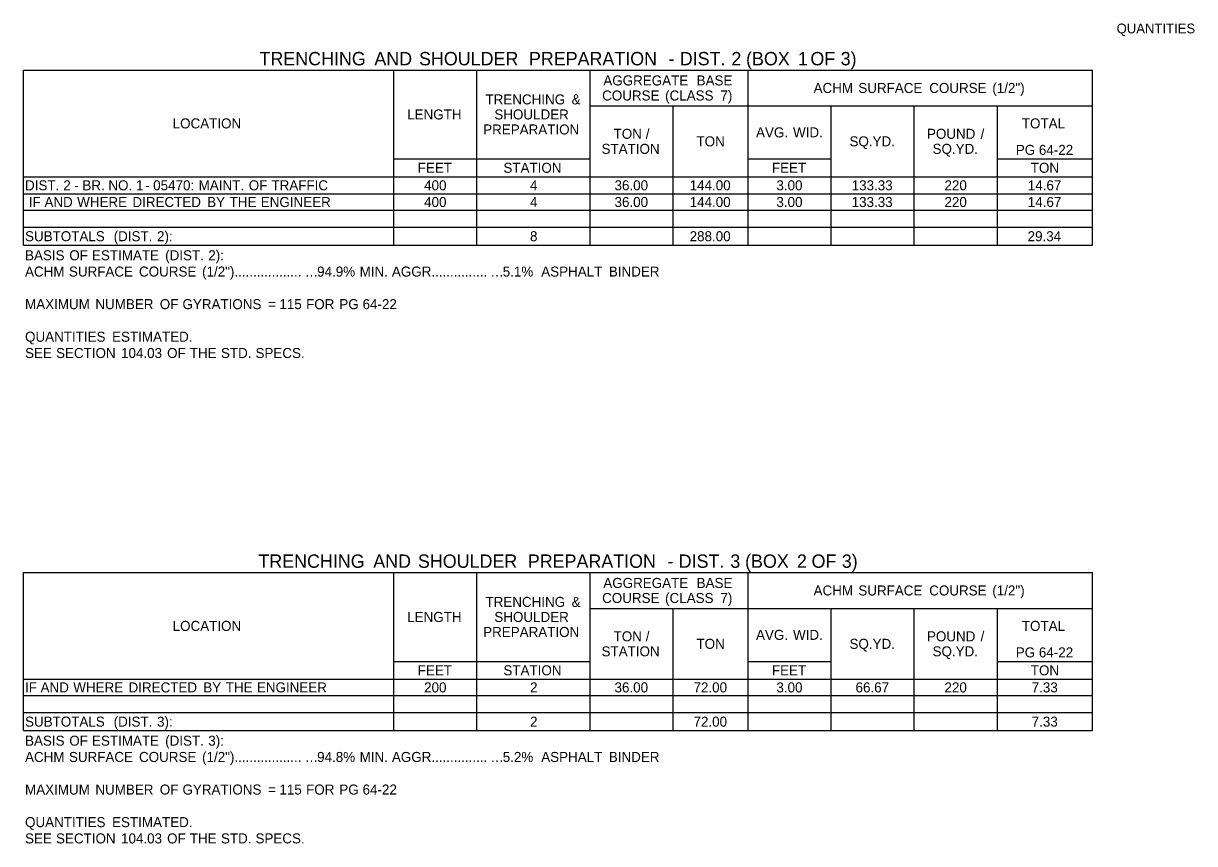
# Model space of a CAD drawing. Extents: x 544250 to 1930787, y -1948365 to 596640.
# Drawn here: x 546909 to 547610, y -1947849 to -1947358 of the extents above; entities that cross this region are included whole.
import ezdxf

# ---------------------------------------------------------------- set-up
doc = ezdxf.new("R2010")
doc.units = 0
doc.layers.add('Default', color=7, linetype='Continuous')
doc.layers.add('R_Border Prem', color=7, linetype='Continuous')

msp = doc.modelspace()

# ---------------------------------------------------------------- linework, layer by layer
at = {"layer": 'Default'}
for p, q in [((546908.73, -1947385.85), (547548.82, -1947385.85)), ((546908.73, -1947490.67), (546908.73, -1947385.85)), ((546908.73, -1947490.67), (546908.73, -1947385.85)), ((547130.54, -1947490.67), (547130.54, -1947385.85)), ((547180.27, -1947490.67), (547180.27, -1947385.85)), ((547248.03, -1947490.67), (547248.03, -1947385.85)), ((547342.61, -1947490.67), (547342.61, -1947385.85)), ((547548.82, -1947490.67), (547548.82, -1947385.85)), ((547548.82, -1947490.67), (547548.82, -1947385.85)), ((547248.03, -1947407.3), (547548.82, -1947407.3)), ((547297.76, -1947490.67), (547297.76, -1947407.3)), ((547392.33, -1947490.67), (547392.33, -1947407.3)), ((547442.06, -1947490.67), (547442.06, -1947407.3)), ((547491.78, -1947490.67), (547491.78, -1947407.3)), ((547130.54, -1947438.99), (547248.03, -1947438.99)), ((547180.27, -1947479.94), (547180.27, -1947438.99)), ((547342.61, -1947438.99), (547392.33, -1947438.99)), ((547342.61, -1947449.72), (547342.61, -1947438.99)), ((547392.33, -1947479.94), (547392.33, -1947438.99)), ((547491.78, -1947438.99), (547548.82, -1947438.99)), ((546908.73, -1947449.72), (547548.82, -1947449.72)), ((547130.54, -1947490.67), (547130.54, -1947449.72)), ((547248.03, -1947449.72), (547392.33, -1947449.72)), ((547248.03, -1947479.94), (547248.03, -1947449.72)), ((547297.76, -1947479.94), (547297.76, -1947449.72)), ((547392.33, -1947449.72), (547548.82, -1947449.72)), ((547442.06, -1947479.94), (547442.06, -1947449.72)), ((547491.78, -1947479.94), (547491.78, -1947449.72)), ((546908.73, -1947459.95), (547548.82, -1947459.95)), ((547491.78, -1947459.95), (547548.82, -1947459.95)), ((546908.73, -1947469.7), (547548.82, -1947469.7)), ((546908.73, -1947479.94), (547548.82, -1947479.94)), ((546908.73, -1947479.94), (547548.82, -1947479.94)), ((546908.73, -1947490.67), (547548.82, -1947490.67)), ((546908.73, -1947686.59), (547548.82, -1947686.59)), ((546908.73, -1947781.16), (546908.73, -1947686.59)), ((546908.73, -1947781.16), (546908.73, -1947686.59)), ((547130.54, -1947781.16), (547130.54, -1947686.59)), ((547180.27, -1947781.16), (547180.27, -1947686.59)), ((547248.03, -1947781.16), (547248.03, -1947686.59)), ((547342.61, -1947781.16), (547342.61, -1947686.59)), ((547548.82, -1947781.16), (547548.82, -1947686.59)), ((547548.82, -1947781.16), (547548.82, -1947686.59)), ((547248.03, -1947708.04), (547548.82, -1947708.04)), ((547297.76, -1947781.16), (547297.76, -1947708.04)), ((547392.33, -1947781.16), (547392.33, -1947708.04)), ((547442.06, -1947781.16), (547442.06, -1947708.04)), ((547491.78, -1947781.16), (547491.78, -1947708.04)), ((547130.54, -1947739.72), (547248.03, -1947739.72)), ((547180.27, -1947770.44), (547180.27, -1947739.72)), ((547342.61, -1947739.72), (547392.33, -1947739.72)), ((547342.61, -1947750.45), (547342.61, -1947739.72)), ((547392.33, -1947770.44), (547392.33, -1947739.72)), ((547491.78, -1947739.72), (547548.82, -1947739.72)), ((546908.73, -1947750.45), (547491.78, -1947750.45)), ((547130.54, -1947781.16), (547130.54, -1947750.45)), ((547248.03, -1947750.45), (547392.33, -1947750.45)), ((547248.03, -1947770.44), (547248.03, -1947750.45)), ((547297.76, -1947770.44), (547297.76, -1947750.45)), ((547392.33, -1947750.45), (547548.82, -1947750.45)), ((547442.06, -1947770.44), (547442.06, -1947750.45)), ((547491.78, -1947750.45), (547548.82, -1947750.45)), ((547491.78, -1947770.44), (547491.78, -1947750.45)), ((546908.73, -1947760.2), (547548.82, -1947760.2)), ((546908.73, -1947770.44), (547548.82, -1947770.44)), ((546908.73, -1947770.44), (547548.82, -1947770.44)), ((546908.73, -1947781.16), (547548.82, -1947781.16))]:
    msp.add_line(p, q, dxfattribs=at)

# ---------------------------------------------------------------- texts
for s, height, p in [('TRENCHING', 8, (547050.07, -1947383.03)), (' AND', 8, (547115.85, -1947383.03)), (' SHOULDER', 8, (547142.61, -1947383.03)), (' PREPARATION', 8, (547208.39, -1947383.03)), (' -', 8, (547291.97, -1947383.03)), (' DIST.', 8, (547298.71, -1947383.03)), (' 2', 8, (547329.61, -1947383.03)), (' (BOX', 8, (547338.37, -1947383.03)), (' 1', 8, (547369.41, -1947383.03)), (' OF', 8, (547376.91, -1947383.03)), (' 3)', 8, (547395.02, -1947383.03)), ('AGGREGATE', 6, (547255.9, -1947395.08)), (' BASE', 6, (547309.53, -1947395.08)), ('ACHM', 6, (547381.78, -1947399.58)), (' SURFACE', 6, (547406.33, -1947399.58)), (' COURSE', 6, (547448.77, -1947399.58)), (' (1/2")', 6, (547486.55, -1947399.58)), ('TRENCHING', 6, (547185.36, -1947406.42)), (' &', 6, (547234.69, -1947406.42)), ('COURSE', 6, (547255.19, -1947404.08)), (' (CLASS', 6, (547290.65, -1947404.08)), (' 7)', 6, (547323.77, -1947404.08)), ('LOCATION', 6, (546998.08, -1947420.78)), ('LENGTH', 6, (547138.49, -1947415.42)), ('SHOULDER', 6, (547190.65, -1947415.42)), ('TOTAL', 6, (547506.45, -1947420.78)), ('PREPARATION', 6, (547183.97, -1947424.42)), ('TON', 6, (547262.05, -1947427.01)), (' /', 6, (547279.07, -1947427.01)), ('AVG.', 6, (547347.32, -1947426.15)), (' WID.', 6, (547367.24, -1947426.15)), ('POUND', 6, (547449.66, -1947427.01)), (' /', 6, (547479.52, -1947427.01)), ('TON', 6, (547311.67, -1947431.51)), ('SQ.YD.', 6, (547403.27, -1947431.51)), ('STATION', 6, (547254.83, -1947436.01)), ('SQ.YD.', 6, (547453, -1947436.01)), ('PG', 6, (547502.83, -1947436.63)), (' 64-22', 6, (547514.43, -1947436.63)), ('FEET', 6, (547144.78, -1947447.35)), ('STATION', 6, (547196.09, -1947447.35)), ('FEET', 6, (547356.84, -1947447.35)), ('TON', 6, (547511.79, -1947447.35)), ('DIST.', 6, (546909.71, -1947457.83)), (' 2', 6, (546930.4, -1947457.83)), (' -', 6, (546936.94, -1947457.83)), (' BR.', 6, (546941.8, -1947457.83)), (' NO.', 6, (546957.37, -1947457.83)), (' 1', 6, (546973.87, -1947457.83)), (' -', 6, (546979.32, -1947457.83)), (' 05470:', 6, (546984.18, -1947457.83)), (' MAINT.', 6, (547011.4, -1947457.83)), (' OF', 6, (547041.4, -1947457.83)), (' TRAFFIC', 6, (547054.99, -1947457.83)), ('400', 6, (547148.62, -1947457.83)), ('4', 6, (547212.02, -1947457.83)), ('36.00', 6, (547262.61, -1947457.83)), ('144.00', 6, (547307.57, -1947457.83)), ('3.00', 6, (547359.52, -1947457.83)), ('133.33', 6, (547404.57, -1947457.83)), ('220', 6, (547460.13, -1947457.83)), ('14.67', 6, (547510.01, -1947457.83)), (' IF', 6, (546909.71, -1947467.83)), (' AND', 6, (546919.1, -1947467.83)), (' WHERE', 6, (546938.68, -1947467.83)), (' DIRECTED', 6, (546971.77, -1947467.83)), (' BY', 6, (547016.5, -1947467.83)), (' THE', 6, (547029.95, -1947467.83)), (' ENGINEER', 6, (547048.6, -1947467.83)), ('400', 6, (547148.62, -1947467.83)), ('4', 6, (547212.02, -1947467.83)), ('36.00', 6, (547262.61, -1947467.83)), ('144.00', 6, (547307.57, -1947467.83)), ('3.00', 6, (547359.52, -1947467.83)), ('133.33', 6, (547404.57, -1947467.83)), ('220', 6, (547460.13, -1947467.83)), ('14.67', 6, (547510.01, -1947467.83)), ('SUBTOTALS', 6, (546909.71, -1947488.3)), (' (DIST.', 6, (546960.53, -1947488.3)), (' 2):', 6, (546986.5, -1947488.3)), ('8', 6, (547212.01, -1947488.3)), ('288.00', 6, (547307.57, -1947488.3)), ('29.34', 6, (547509.91, -1947488.3)), ('BASIS', 6, (546909.71, -1947499.7)), (' OF', 6, (546933.97, -1947499.7)), (' ESTIMATE', 6, (546947.55, -1947499.7)), (' (DIST.', 6, (546991.36, -1947499.7)), (' 2):', 6, (547017.17, -1947499.7)), ('ACHM', 6, (546909.71, -1947509.45)), (' SURFACE', 6, (546933.76, -1947509.45)), (' COURSE', 6, (546975.71, -1947509.45)), (' (1/2")..................', 6, (547013.46, -1947509.45)), ('94.9%', 6, (547084.56, -1947509.45)), (' MIN.', 6, (547107.8, -1947509.45)), (' AGGR...............', 6, (547127.09, -1947509.45)), ('5.1%', 6, (547195.69, -1947509.45)), ('  ASPHALT', 6, (547214.27, -1947509.45)), (' BINDER', 6, (547256.97, -1947509.45)), ('…', 6, (547077.16, -1947509.45)), ('…', 6, (547188.29, -1947509.45)), ('MAXIMUM', 6, (546909.71, -1947528.95)), (' NUMBER', 6, (546949.59, -1947528.95)), (' OF', 6, (546988.14, -1947528.95)), (' GYRATIONS', 6, (547001.73, -1947528.95)), (' =', 6, (547053, -1947528.95)), (' 115', 6, (547059.75, -1947528.95)), (' FOR', 6, (547075.73, -1947528.95)), (' PG', 6, (547095.64, -1947528.95)), (' 64-22', 6, (547109.55, -1947528.95)), ('QUANTITIES', 6, (546909.71, -1947548.45)), (' ESTIMATED.', 6, (546959.58, -1947548.45)), ('SEE', 6, (546909.71, -1947558.2)), (' SECTION', 6, (546926.04, -1947558.2)), (' 104.03', 6, (546964.95, -1947558.2)), (' OF', 6, (546992.52, -1947558.2)), (' THE', 6, (547006.11, -1947558.2)), (' STD.', 6, (547024.76, -1947558.2)), (' SPECS.', 6, (547045.45, -1947558.2)), ('TRENCHING', 8, (547049.41, -1947683.76)), (' AND', 8, (547115.18, -1947683.76)), (' SHOULDER', 8, (547141.95, -1947683.76)), (' PREPARATION', 8, (547207.73, -1947683.76)), (' -', 8, (547291.3, -1947683.76)), (' DIST.', 8, (547298.05, -1947683.76)), (' 3', 8, (547328.95, -1947683.76)), (' (BOX', 8, (547337.78, -1947683.76)), (' 2', 8, (547368.82, -1947683.76)), (' OF', 8, (547377.58, -1947683.76)), (' 3)', 8, (547395.69, -1947683.76)), ('AGGREGATE', 6, (547255.9, -1947695.81)), (' BASE', 6, (547309.53, -1947695.81)), ('ACHM', 6, (547381.78, -1947700.31)), (' SURFACE', 6, (547406.33, -1947700.31)), (' COURSE', 6, (547448.77, -1947700.31)), (' (1/2")', 6, (547486.55, -1947700.31)), ('TRENCHING', 6, (547185.36, -1947707.15)), (' &', 6, (547234.69, -1947707.15)), ('COURSE', 6, (547255.19, -1947704.81)), (' (CLASS', 6, (547290.65, -1947704.81)), (' 7)', 6, (547323.77, -1947704.81)), ('LENGTH', 6, (547138.49, -1947716.15)), ('SHOULDER', 6, (547190.65, -1947716.15)), ('LOCATION', 6, (546998.08, -1947721.52)), ('TOTAL', 6, (547506.45, -1947721.52)), ('PREPARATION', 6, (547183.97, -1947725.15)), ('TON', 6, (547262.05, -1947727.74)), (' /', 6, (547279.07, -1947727.74)), ('AVG.', 6, (547347.32, -1947726.88)), (' WID.', 6, (547367.24, -1947726.88)), ('POUND', 6, (547449.66, -1947727.74)), (' /', 6, (547479.52, -1947727.74)), ('STATION', 6, (547254.83, -1947736.74)), ('TON', 6, (547311.67, -1947732.24)), ('SQ.YD.', 6, (547403.27, -1947732.24)), ('SQ.YD.', 6, (547453, -1947736.74)), ('PG', 6, (547502.83, -1947737.36)), (' 64-22', 6, (547514.43, -1947737.36)), ('FEET', 6, (547144.78, -1947748.09)), ('STATION', 6, (547196.09, -1947748.09)), ('FEET', 6, (547356.84, -1947748.09)), ('TON', 6, (547511.79, -1947748.09)), (' DIRECTED', 6, (546969.44, -1947758.32)), (' ENGINEER', 6, (547046.27, -1947758.32)), ('200', 6, (547148.62, -1947758.32)), ('2', 6, (547212.04, -1947758.32)), ('36.00', 6, (547262.61, -1947758.32)), ('72.00', 6, (547309.9, -1947758.32)), ('3.00', 6, (547359.52, -1947758.32)), ('66.67', 6, (547406.9, -1947758.32)), ('220', 6, (547460.13, -1947758.32)), ('7.33', 6, (547512.34, -1947758.32)), ('IF', 6, (546909.71, -1947758.32)), (' AND', 6, (546916.77, -1947758.32)), (' WHERE', 6, (546936.35, -1947758.32)), (' BY', 6, (547014.18, -1947758.32)), (' THE', 6, (547027.63, -1947758.32)), ('SUBTOTALS', 6, (546909.71, -1947778.8)), (' (DIST.', 6, (546960.53, -1947778.8)), (' 3):', 6, (546986.5, -1947778.8)), ('2', 6, (547212.03, -1947778.8)), ('72.00', 6, (547309.9, -1947778.8)), ('7.33', 6, (547512.33, -1947778.8)), ('BASIS', 6, (546909.71, -1947790.2)), (' OF', 6, (546933.97, -1947790.2)), (' ESTIMATE', 6, (546947.55, -1947790.2)), (' (DIST.', 6, (546991.36, -1947790.2)), (' 3):', 6, (547017.17, -1947790.2)), ('ACHM', 6, (546909.71, -1947799.95)), (' SURFACE', 6, (546933.76, -1947799.95)), (' COURSE', 6, (546975.71, -1947799.95)), (' (1/2")..................', 6, (547013.46, -1947799.95)), ('94.8%', 6, (547084.56, -1947799.95)), (' MIN.', 6, (547107.8, -1947799.95)), (' AGGR...............', 6, (547127.09, -1947799.95)), ('5.2%', 6, (547195.69, -1947799.95)), ('  ASPHALT', 6, (547214.27, -1947799.95)), (' BINDER', 6, (547256.97, -1947799.95)), ('…', 6, (547077.16, -1947799.95)), ('…', 6, (547188.29, -1947799.95)), ('MAXIMUM', 6, (546909.71, -1947819.45)), (' NUMBER', 6, (546949.59, -1947819.45)), (' OF', 6, (546988.14, -1947819.45)), (' GYRATIONS', 6, (547001.73, -1947819.45)), (' =', 6, (547053, -1947819.45)), (' 115', 6, (547059.75, -1947819.45)), (' FOR', 6, (547075.73, -1947819.45)), (' PG', 6, (547095.64, -1947819.45)), (' 64-22', 6, (547109.55, -1947819.45)), ('QUANTITIES', 6, (546909.71, -1947838.95)), (' ESTIMATED.', 6, (546959.58, -1947838.95)), ('SEE', 6, (546909.71, -1947848.7)), (' SECTION', 6, (546926.04, -1947848.7)), (' 104.03', 6, (546964.95, -1947848.7)), (' OF', 6, (546992.52, -1947848.7)), (' THE', 6, (547006.11, -1947848.7)), (' STD.', 6, (547024.76, -1947848.7)), (' SPECS.', 6, (547045.45, -1947848.7))]:
    msp.add_text(s, height=height, dxfattribs=at).set_placement(p)
at = {"layer": 'R_Border Prem'}
msp.add_text('QUANTITIES', height=5.862, rotation=360, dxfattribs=at).set_placement((547563.18, -1947363.9))

doc.saveas('drawing.dxf')
